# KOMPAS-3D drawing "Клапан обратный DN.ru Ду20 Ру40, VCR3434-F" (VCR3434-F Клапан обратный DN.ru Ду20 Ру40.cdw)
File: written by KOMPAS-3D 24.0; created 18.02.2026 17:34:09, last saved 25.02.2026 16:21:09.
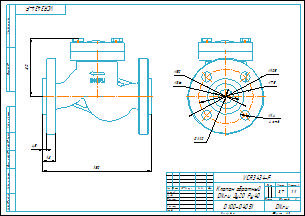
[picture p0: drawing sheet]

Document properties: art: D100-04051; Автор: R2D2; Форматы листов документа: A3; Полное имя файла: VCR3434-F Клапан обратный DN.ru Ду20 Ру40.m3d; Масса: 3.7; Наименование: Клапан обратный DN.ru Ду20 Ру40; Количество листов документа: 1; Примечание: D100-04051

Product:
- Body: Тело 2  | qty 1
    Масса: 4.256857
- Part/product: Клапан обратный DN.ru Ду20 Ру40  | designation VCR3434-F
    Масса: 3.7
    Раздел спецификации: Прочие изделия
    Примечание: D100-04051
    additional columns: D100-04051

Views: Вид 1, Справа, Проекционный вид 2
Referenced files in E:\Работа\Зайцев\VCR3434-F Клапан обратный DN.ru Ду15-300\DN20\: VCR3434-F Клапан обратный DN.ru Ду20 Ру40.m3d
Referenced files in E:\Работа\Зайцев\Для компаса\: чертеж DN.ru А3.cdt
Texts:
  VCR3434-F
  чертеж DN.ru А3.cdt
  Клапан обратный
  DN.ru Ду20 Ру40
  prop
  Клапан обратный DN.ru Ду20 Ру40
  VCR3434-F Клапан обратный DN.ru Ду20 Ру40
Dimensions and other numbers on the sheet: 0; 3; 2; 4; 4,5; 18; 150; 80; 105; 75; 14; 4 отв.; 20; 36; 50; 1:1; 1; 3,7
